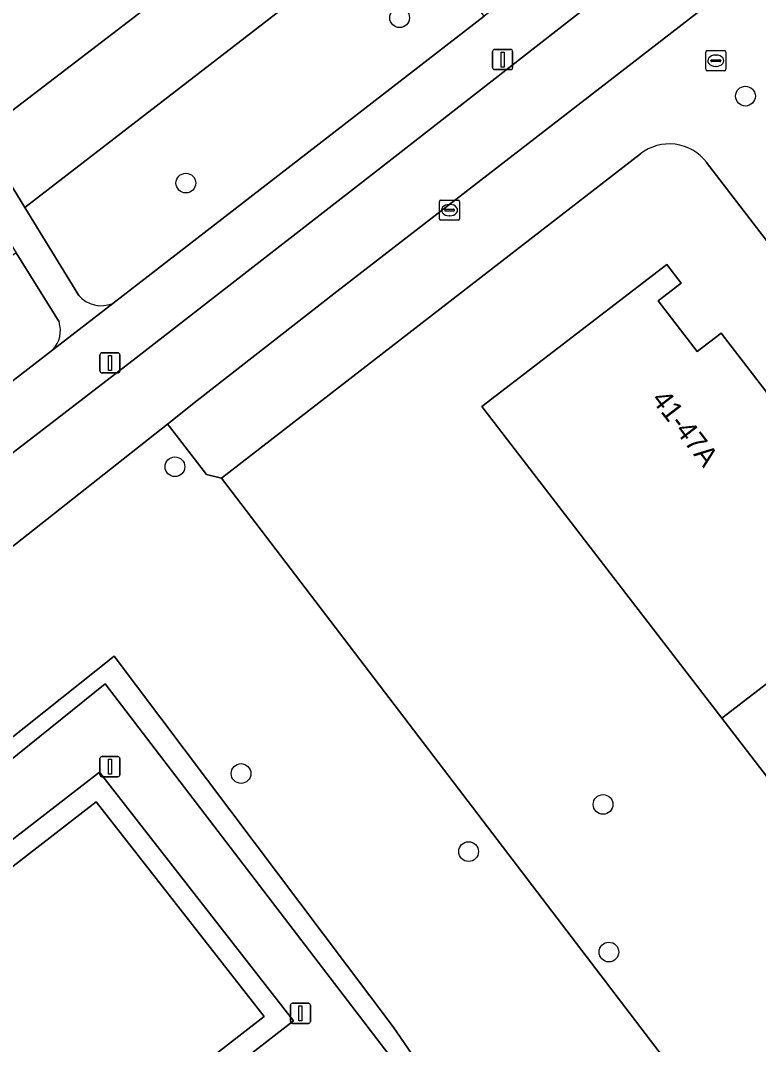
# Model space of a CAD drawing. Extents: x 159352 to 160617, y 385888 to 387323.
# Drawn here: x 159888.1 to 159924.7, y 386579.2 to 386630 of the extents above; entities that cross this region are included whole.
import ezdxf

# ---------------------------------------------------------------- set-up
doc = ezdxf.new("R2010")
doc.units = 0
for name, color, linetype in [('IMGEO_Boom', 7, 'Continuous'), ('IMGEO_Brandkraan', 7, 'Continuous'), ('IMGEO_Erf', 7, 'Continuous'), ('IMGEO_Groenvoorziening', 7, 'Continuous'), ('IMGEO_Haag', 7, 'Continuous'), ('IMGEO_Kolk', 7, 'Continuous'), ('IMGEO_Lichtmast', 7, 'Continuous'), ('IMGEO_Pand', 7, 'Continuous'), ('IMGEO_Pand_nummerreeks', 7, 'Continuous'), ('IMGEO_Voetpad_halfverhard', 7, 'Continuous'), ('IMGEO_Voetpad_open', 7, 'Continuous')]:
    doc.layers.add(name, color=color, linetype=linetype)

msp = doc.modelspace()

# ---------------------------------------------------------------- linework, layer by layer
at = {"layer": 'IMGEO_Boom'}
for centre in [(159906.918, 386630.129), (159924.064, 386626.243), (159896.318, 386621.931), (159895.776, 386607.863), (159899.053, 386592.651), (159917.002, 386591.118), (159910.336, 386588.779), (159917.291, 386583.8)]:
    msp.add_circle(centre, 0.489, dxfattribs=at)
at = {"layer": 'IMGEO_Brandkraan'}
for p, q in [((159922.093, 386627.574), (159922.093, 386628.426)), ((159922.168, 386628.5), (159923.02, 386628.5)), ((159923.094, 386628.426), (159923.094, 386627.574)), ((159922.352, 386627.994), (159922.352, 386628.006)), ((159922.79, 386627.957), (159922.392, 386627.957)), ((159922.395, 386628.043), (159922.793, 386628.043)), ((159922.581, 386628.28), (159922.606, 386628.28)), ((159922.836, 386628.006), (159922.836, 386627.994)), ((159923.02, 386627.5), (159922.168, 386627.5)), ((159922.604, 386627.72), (159922.579, 386627.72))]:
    msp.add_line(p, q, dxfattribs=at)
for points in [[(159922.093, 386627.574), (159922.093, 386628.426)], [(159922.168, 386628.5), (159923.02, 386628.5)], [(159923.094, 386628.426), (159923.094, 386627.574)], [(159923.02, 386627.5), (159922.168, 386627.5)]]:
    msp.add_lwpolyline(points, dxfattribs=at)
for centre, radius, start, end in [((159922.17, 386628.424), 0.0765, 91.552, 178.448), ((159922.17, 386628.424), 0.0765, 91.552, 178.448), ((159923.018, 386628.424), 0.0765, 1.552, 88.448), ((159923.018, 386628.424), 0.0765, 1.552, 88.448), ((159922.392, 386628.003), 0.0403, 85.8775, 175.7526), ((159922.389, 386627.993), 0.0366, 178.938, 274.7102), ((159922.793, 386628), 0.043, 264.8664, 352.4533), ((159922.797, 386628.005), 0.0386, 1.7309, 96.639), ((159922.17, 386627.576), 0.0765, 181.552, 268.448), ((159922.17, 386627.576), 0.0765, 181.552, 268.448), ((159923.018, 386627.576), 0.0765, 271.552, 358.448), ((159923.018, 386627.576), 0.0765, 271.552, 358.448)]:
    msp.add_arc(centre, radius, start, end, dxfattribs=at)
for centre, major_axis, ratio, start_param, end_param in [((159922.58, 386628), (-0.387, 0.002), 0.722429, 4.712389, 7.853982), ((159922.605, 386628), (-0.39, 0.002), 0.717154, 1.570796, 4.712389)]:
    msp.add_ellipse(centre, major_axis=major_axis, ratio=ratio, start_param=start_param, end_param=end_param, dxfattribs=at)
at = {"layer": 'IMGEO_Erf'}
for points in [[(159883.277, 386633.788), (159885.754, 386629.839), (159883.459, 386628.399), (159884.746, 386626.56), (159886.127, 386624.321), (159912.319, 386644.386)], [(159918.853, 386623.383), (159898.089, 386607.292), (159922.277, 386575.578), (159940.008, 386552.331), (159951.895, 386536.745), (159972.553, 386552.445)], [(159973.106, 386556.66), (159922.14, 386622.955)], [(159934.791, 386579.947), (159922.892, 386595.396), (159910.993, 386610.845), (159920.17, 386617.896), (159920.88, 386616.972), (159919.737, 386616.094), (159921.673, 386613.575), (159922.862, 386614.489), (159927.223, 386608.814)], [(159887.525, 386548.869), (159885.213, 386553.204), (159883.085, 386565.997), (159873.436, 386578.327), (159892.035, 386592.722), (159901.662, 386580.391), (159884.455, 386567.051), (159886.557, 386554.32), (159900.837, 386565.265), (159903.749, 386561.385), (159912.832, 386568.343), (159908.045, 386576.538), (159892.32, 386597.107), (159870.65, 386579.64), (159860.843, 386571.736), (159835.685, 386551.458)]]:
    msp.add_lwpolyline(points, dxfattribs=at)
msp.add_arc((159920.284, 386621.537), 2.336, 37.3852, 127.7773, dxfattribs=at)
at = {"layer": 'IMGEO_Groenvoorziening'}
for points in [[(159907.285, 386635.368), (159914.84, 386641.104), (159912.319, 386644.386), (159886.127, 386624.321), (159888.339, 386620.715)], [(159906.593, 386580.097), (159892.764, 386598.468), (159870.125, 386580.456), (159848.013, 386563.682), (159832.901, 386551.867), (159853.08, 386512.967), (159868.235, 386520.386), (159868.151, 386520.851), (159867.933, 386521.114), (159853.233, 386513.876), (159849.751, 386521.402), (159848.127, 386524.605), (159846.503, 386527.808), (159846.696, 386527.931), (159835.685, 386551.458), (159860.843, 386571.736), (159870.65, 386579.64), (159892.32, 386597.107), (159908.045, 386576.538), (159912.832, 386568.343), (159913.328, 386568.723), (159911.532, 386572.899)]]:
    msp.add_lwpolyline(points, close=True, dxfattribs=at)
for points in [[(159911.115, 386630.215), (159907.285, 386635.368), (159888.339, 386620.715), (159891.01, 386616.361)], [(159892.693, 386615.968), (159911.115, 386630.215)], [(159890.032, 386615.044), (159887.9, 386618.48), (159864.765, 386601.856), (159867.91, 386596.802), (159889.72, 386613.668)], [(159951.895, 386536.745), (159940.008, 386552.331), (159922.277, 386575.578), (159898.089, 386607.292), (159897.345, 386607.476), (159895.505, 386609.853), (159895.402, 386609.984), (159883.468, 386600.561), (159865.36, 386586.583)], [(159848.013, 386563.682), (159870.125, 386580.456), (159892.764, 386598.468), (159906.593, 386580.097), (159911.532, 386572.899), (159913.328, 386568.723), (159917.807, 386562.877), (159918.33, 386563.284), (159920.36, 386564.743), (159933.568, 386547.368)]]:
    msp.add_lwpolyline(points, dxfattribs=at)
for centre, radius, start, end in [((159892.116, 386617.296), 1.448, 220.219, 293.4936), ((159888.718, 386614.618), 1.381, 316.4981, 17.9509)]:
    msp.add_arc(centre, radius, start, end, dxfattribs=at)
at = {"layer": 'IMGEO_Haag'}
msp.add_lwpolyline([(159835.685, 386551.458), (159860.843, 386571.736), (159870.65, 386579.64), (159892.32, 386597.107), (159908.045, 386576.538), (159912.832, 386568.343), (159913.328, 386568.723), (159911.532, 386572.899), (159906.593, 386580.097), (159892.764, 386598.468), (159870.125, 386580.456), (159848.013, 386563.682), (159832.901, 386551.867), (159853.08, 386512.967), (159868.235, 386520.386), (159868.151, 386520.851), (159867.933, 386521.114), (159853.233, 386513.876), (159849.751, 386521.402), (159848.127, 386524.605), (159846.503, 386527.808), (159846.696, 386527.931)], close=True, dxfattribs=at)
at = {"layer": 'IMGEO_Kolk'}
for p, q in [((159908.892, 386620.164), (159908.892, 386621.016)), ((159908.967, 386621.09), (159909.819, 386621.09)), ((159909.38, 386620.87), (159909.405, 386620.87)), ((159909.893, 386621.016), (159909.893, 386620.164)), ((159909.151, 386620.584), (159909.151, 386620.596)), ((159909.589, 386620.547), (159909.191, 386620.547)), ((159909.194, 386620.633), (159909.592, 386620.633)), ((159909.403, 386620.31), (159909.378, 386620.31)), ((159909.635, 386620.596), (159909.635, 386620.584)), ((159909.819, 386620.09), (159908.967, 386620.09))]:
    msp.add_line(p, q, dxfattribs=at)
for points in [[(159908.892, 386620.164), (159908.892, 386621.016)], [(159908.967, 386621.09), (159909.819, 386621.09)], [(159909.893, 386621.016), (159909.893, 386620.164)], [(159909.819, 386620.09), (159908.967, 386620.09)]]:
    msp.add_lwpolyline(points, dxfattribs=at)
for centre, radius, start, end in [((159908.969, 386621.014), 0.0765, 91.552, 178.448), ((159908.969, 386621.014), 0.0765, 91.552, 178.448), ((159909.817, 386621.014), 0.0765, 1.552, 88.448), ((159909.817, 386621.014), 0.0765, 1.552, 88.448), ((159909.191, 386620.593), 0.0403, 85.8775, 175.7526), ((159909.188, 386620.583), 0.0366, 178.938, 274.7102), ((159909.592, 386620.59), 0.043, 264.8664, 352.4533), ((159909.596, 386620.595), 0.0386, 1.7309, 96.639), ((159908.969, 386620.166), 0.0765, 181.552, 268.448), ((159908.969, 386620.166), 0.0765, 181.552, 268.448), ((159909.817, 386620.166), 0.0765, 271.552, 358.448), ((159909.817, 386620.166), 0.0765, 271.552, 358.448)]:
    msp.add_arc(centre, radius, start, end, dxfattribs=at)
for centre, major_axis, ratio, start_param, end_param in [((159909.379, 386620.59), (-0.387, 0.002), 0.722429, 4.712389, 7.853982), ((159909.404, 386620.59), (-0.39, 0.002), 0.717154, 1.570796, 4.712389)]:
    msp.add_ellipse(centre, major_axis=major_axis, ratio=ratio, start_param=start_param, end_param=end_param, dxfattribs=at)
at = {"layer": 'IMGEO_Lichtmast'}
for p, q in [((159911.528, 386627.657), (159911.528, 386628.457)), ((159911.528, 386628.457), (159911.528, 386627.657)), ((159911.628, 386628.557), (159912.418, 386628.557)), ((159912.418, 386628.557), (159911.628, 386628.557)), ((159912.518, 386628.457), (159912.518, 386627.657)), ((159912.518, 386627.657), (159912.518, 386628.457)), ((159912.418, 386627.557), (159911.628, 386627.557)), ((159911.628, 386627.557), (159912.418, 386627.557)), ((159892.055, 386612.614), (159892.055, 386613.414)), ((159892.055, 386613.414), (159892.055, 386612.614)), ((159892.155, 386613.514), (159892.945, 386613.514)), ((159892.945, 386613.514), (159892.155, 386613.514)), ((159893.045, 386613.414), (159893.045, 386612.614)), ((159893.045, 386612.614), (159893.045, 386613.414)), ((159892.945, 386612.514), (159892.155, 386612.514)), ((159892.155, 386612.514), (159892.945, 386612.514)), ((159892.058, 386592.588), (159892.058, 386593.388)), ((159892.058, 386593.388), (159892.058, 386592.588)), ((159892.158, 386593.488), (159892.948, 386593.488)), ((159892.948, 386593.488), (159892.158, 386593.488)), ((159893.048, 386593.388), (159893.048, 386592.588)), ((159893.048, 386592.588), (159893.048, 386593.388)), ((159892.948, 386592.488), (159892.158, 386592.488)), ((159892.158, 386592.488), (159892.948, 386592.488)), ((159901.503, 386580.361), (159901.503, 386581.161)), ((159901.503, 386581.161), (159901.503, 386580.361)), ((159901.603, 386581.261), (159902.393, 386581.261)), ((159902.393, 386581.261), (159901.603, 386581.261)), ((159902.493, 386581.161), (159902.493, 386580.361)), ((159902.493, 386580.361), (159902.493, 386581.161)), ((159902.393, 386580.261), (159901.603, 386580.261)), ((159901.603, 386580.261), (159902.393, 386580.261))]:
    msp.add_line(p, q, dxfattribs=at)
for points in [[(159911.948, 386628.432), (159912.098, 386628.432), (159912.098, 386627.682), (159911.948, 386627.682), (159911.948, 386628.432)], [(159892.475, 386613.389), (159892.625, 386613.389), (159892.625, 386612.639), (159892.475, 386612.639), (159892.475, 386613.389)], [(159892.478, 386593.363), (159892.628, 386593.363), (159892.628, 386592.613), (159892.478, 386592.613), (159892.478, 386593.363)], [(159901.923, 386581.136), (159902.073, 386581.136), (159902.073, 386580.386), (159901.923, 386580.386), (159901.923, 386581.136)]]:
    msp.add_lwpolyline(points, dxfattribs=at)
for centre, start, end in [((159911.628, 386628.457), 90, 180), ((159911.628, 386628.457), 90, 180), ((159912.418, 386628.457), 0, 90), ((159912.418, 386628.457), 360, 90), ((159911.628, 386627.657), 180, 270), ((159911.628, 386627.657), 180, 270), ((159912.418, 386627.657), 270, 0), ((159912.418, 386627.657), 270, 0), ((159892.155, 386613.414), 90, 180), ((159892.155, 386613.414), 90, 180), ((159892.945, 386613.414), 0, 90), ((159892.945, 386613.414), 360, 90), ((159892.155, 386612.614), 180, 270), ((159892.155, 386612.614), 180, 270), ((159892.945, 386612.614), 270, 0), ((159892.945, 386612.614), 270, 0), ((159892.158, 386593.388), 90, 180), ((159892.158, 386593.388), 90, 180), ((159892.948, 386593.388), 0, 90), ((159892.948, 386593.388), 360, 90), ((159892.158, 386592.588), 180, 270), ((159892.158, 386592.588), 180, 270), ((159892.948, 386592.588), 270, 0), ((159892.948, 386592.588), 270, 0), ((159901.603, 386581.161), 90, 180), ((159901.603, 386581.161), 90, 180), ((159902.393, 386581.161), 0, 90), ((159902.393, 386581.161), 360, 90), ((159901.603, 386580.361), 180, 270), ((159901.603, 386580.361), 180, 270), ((159902.393, 386580.361), 270, 0), ((159902.393, 386580.361), 270, 0)]:
    msp.add_arc(centre, 0.1, start, end, dxfattribs=at)
at = {"layer": 'IMGEO_Pand'}
for points in [[(159929.328, 386606.085), (159928.137, 386605.169), (159926.037, 386607.902), (159927.223, 386608.814), (159922.862, 386614.489), (159921.673, 386613.575), (159919.737, 386616.094), (159920.88, 386616.972), (159920.17, 386617.896), (159910.993, 386610.845), (159922.892, 386595.396), (159932.103, 386602.473)], [(159934.791, 386579.947), (159943.983, 386587.01), (159943.473, 386587.674), (159942.289, 386586.764), (159940.33, 386589.313), (159941.517, 386590.226), (159937.108, 386595.964), (159935.939, 386595.066), (159933.826, 386597.815), (159934.993, 386598.712), (159932.103, 386602.473), (159922.892, 386595.396)]]:
    msp.add_lwpolyline(points, close=True, dxfattribs=at)
at = {"layer": 'IMGEO_Voetpad_halfverhard'}
msp.add_lwpolyline([(159900.194, 386580.602), (159891.872, 386591.255), (159874.947, 386578.146), (159883.292, 386567.488)], close=True, dxfattribs=at)
at = {"layer": 'IMGEO_Voetpad_open'}
for points in [[(159888.339, 386620.715), (159886.127, 386624.321), (159884.746, 386626.56), (159883.459, 386628.399), (159880.98, 386632.35), (159878.506, 386636.294), (159876.701, 386639.169), (159876.024, 386638.744), (159875.41, 386638.359), (159877.206, 386635.496), (159879.687, 386631.541), (159882.164, 386627.593), (159883.338, 386625.815), (159884.716, 386623.61), (159887.9, 386618.48), (159890.032, 386615.044)], [(159869.096, 386594.185), (159873.236, 386597.377), (159877.264, 386600.51), (159886.664, 386607.739), (159893.849, 386613.258), (159905.715, 386622.497), (159920.444, 386634.001), (159916.862, 386638.473), (159916.861, 386638.473)], [(159916.309, 386634.231), (159911.115, 386630.215), (159892.693, 386615.968), (159889.72, 386613.668), (159867.91, 386596.802), (159866.854, 386595.985), (159866.704, 386595.876), (159860.518, 386591.256), (159860.514, 386591.259), (159855.337, 386587.769), (159847.115, 386582.957), (159844.748, 386581.785), (159811.594, 386565.163), (159809.376, 386564.045), (159805.918, 386562.302), (159797.7, 386562.907), (159799.359, 386559.682), (159804.646, 386559.089)], [(159920.909, 386634.364), (159920.444, 386634.001), (159905.715, 386622.497), (159893.849, 386613.258), (159886.664, 386607.739), (159877.264, 386600.51), (159873.236, 386597.377), (159869.096, 386594.185), (159866.761, 386592.415)], [(159922.937, 386631.272), (159921.658, 386630.358), (159903.806, 386616.561), (159896.886, 386611.156), (159895.402, 386609.984), (159895.505, 386609.853), (159897.345, 386607.476), (159898.089, 386607.292), (159918.853, 386623.383)], [(159903.806, 386616.561), (159921.658, 386630.358), (159922.937, 386631.272)], [(159922.14, 386622.955), (159973.106, 386556.66)], [(159891.01, 386616.361), (159888.339, 386620.715)], [(159865.36, 386586.583), (159883.468, 386600.561), (159895.402, 386609.984), (159896.886, 386611.156), (159903.806, 386616.561)], [(159889.72, 386613.668), (159892.693, 386615.968)]]:
    msp.add_lwpolyline(points, dxfattribs=at)
for points in [[(159901.662, 386580.391), (159892.035, 386592.722), (159873.436, 386578.327), (159883.085, 386565.997), (159885.213, 386553.204), (159887.525, 386548.869), (159887.755, 386549.136), (159892.959, 386539.25), (159895.139, 386536.363), (159894.642, 386535.988), (159896.116, 386534.035), (159897.179, 386534.822), (159897.087, 386534.942), (159898.46, 386535.994), (159895.04, 386540.46), (159894.222, 386539.834), (159891.905, 386544.265), (159888.901, 386550.01), (159903.749, 386561.385), (159900.837, 386565.265), (159886.557, 386554.32), (159884.455, 386567.051)], [(159883.292, 386567.488), (159874.947, 386578.146), (159891.872, 386591.255), (159900.194, 386580.602)]]:
    msp.add_lwpolyline(points, close=True, dxfattribs=at)
for centre, radius, start, end in [((159920.284, 386621.537), 2.336, 37.3852, 127.7773), ((159892.116, 386617.296), 1.448, 220.219, 293.4936), ((159888.718, 386614.618), 1.381, 316.4981, 17.9509)]:
    msp.add_arc(centre, radius, start, end, dxfattribs=at)

# ---------------------------------------------------------------- texts
at = {"layer": 'IMGEO_Pand_nummerreeks'}
msp.add_text('41-47A', height=1, rotation=307.5696, dxfattribs=at).set_placement((159919.367, 386611.193))

doc.saveas('drawing.dxf')
